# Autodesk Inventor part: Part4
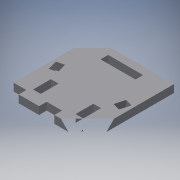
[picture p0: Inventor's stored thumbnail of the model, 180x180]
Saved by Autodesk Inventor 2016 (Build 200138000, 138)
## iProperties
Created: 2017-06
Part Number: Part4
Material: Generic
Document SubType Name: Modeling
Designer: laboratorioesan
Density: 1 g/cm^3
Appearance: Default
Author: laboratorioesan
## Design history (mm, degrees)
sketch "Sketch1"
  geometry: L1 (5, 0)-(5, 3) reference; L2 (-27, 0)-(-27, 3) reference; L3 (0, 0)-(-8, 0) reference; L4 (0, 0)-(0, 3) reference; L5 (-8, 3)-(0, 3) reference; L6 (-8, 0)-(-8, 3) reference; L7 (-14, 0)-(-22, 0) reference; L8 (-14, 0)-(-14, 3) reference; L9 (-22, 3)-(-14, 3) reference; L10 (-22, 0)-(-22, 3) reference; L11 (-27, 3)-(-27, 34); L12 (-27, 34)-(5, 34); L13 (5, 34)-(5, 3); L14 (-17.85, 3)-(-17.85, 13); L15 (-17.85, 13)-(-4.15, 13); L16 (-4.15, 13)-(-4.15, 3); L17 (-4.15, 4.5)-(-1.15, 4.5); L18 (-1.15, 4.5)-(-1.15, 11.5); L19 (-1.15, 11.5)-(-4.15, 11.5); L20 (-4.15, 11.5)-(-4.15, 4.5); L21 (-17.85, 11.5)-(-20.85, 11.5); L22 (-20.85, 11.5)-(-20.85, 4.5); L23 (-20.85, 4.5)-(-17.85, 4.5); L24 (-17.85, 4.5)-(-17.85, 11.5); L25 (-1.15, 11.5)-(5, 34); L26 (-0.095, 15.358)-(2.798, 14.567); L27 (2.798, 14.567)-(3.853, 18.426); L28 (3.853, 18.426)-(0.959, 19.217); L29 (-0.095, 15.358)-(0.959, 19.217); L30 (-20.85, 11.5)-(-27, 34); L31 (-21.905, 15.358)-(-24.798, 14.567); L32 (-24.798, 14.567)-(-25.853, 18.426); L33 (-25.853, 18.426)-(-22.959, 19.217); L34 (-22.959, 19.217)-(-21.905, 15.358); L35 (5, 3)-(0, 3); L36 (-27, 3)-(-22.2, 3); L37 (-22.2, 3)-(-22.2, 0); L38 (-22.2, 0)-(-13.8, 0); L39 (-13.8, 0)-(-13.8, 3); L40 (-13.8, 3)-(-8.2, 3); L41 (-8.2, 3)-(-8.2, 0); L42 (-8.2, 0)-(0.2, 0); L43 (0.2, 0)-(0.2, 3); 2 further points; 1 other entity
  constraints: 66 end point, 8 perpendicular, 7 parallel, 7 point on line, 4 vertical, 3 horizontal, 3 horizontal alignment, 2 collinear, 2 midpoint, 1 coincident, 1 vertical alignment, 9 other
  dimensions: "d0" = 31 distance of L11.start L11.end; "d5" = 13.7 distance of L14.end L15.end; "d6" = 10 distance of L14.start L14.end; "d7" = 3 distance of L19.end L18.end; "d8" = 7 distance of L18.end L17.end; "d9" = 1.5 distance from line of L5 L17.end; "d10" = 3 distance of L23.end L22.end; "d11" = 3 distance of L26.start L26.end; "d12" = 4 distance of L26.end L27.end; "d16" = 4 distance of L18.end L26.start; "d20" = 1.5 distance of L14.end L21.start; "d23" = 3 distance of L31.start L31.end; "d24" = 4 distance of L31.end L32.end; "d25" = 0.2 distance of L3.start L42.end; "d26" = 0.2 distance of L3.end L41.end; "d27" = 0.2 distance of L7.start L38.end; "d28" = 0.2 distance from line of L10 L37.end
extrude "Extrusion1" new body sketch "Sketch1" distance "d29" = 3; taper "d30" = 0 deg
sketch "Sketch2"
  geometry: L1 (20.85, 13)-(17.85, 13) reference; L2 (4.15, 11.7)-(4.15, 4.3) reference; L3 (17.85, 28)-(4.15, 28); L4 (4.15, 28)-(4.15, 31); L5 (4.15, 31)-(17.85, 31); L6 (17.85, 31)-(17.85, 28); 1 further point
  constraints: 12 end point, 2 horizontal, 2 parallel, 1 perpendicular, 1 vertical, 4 other
  dimensions: "d31" = 3 distance of L3.end L4.end; "d32" = 15 distance of L1.end L3.start
extrude "Extrusion2" cut sketch "Sketch2" distance "d33" = 3; taper "d34" = 0 deg
body "Solid1"
node "Reference1"
node "Reference2"
node "Reference3"
